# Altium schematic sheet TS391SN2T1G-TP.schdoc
size 127 x 101 mm
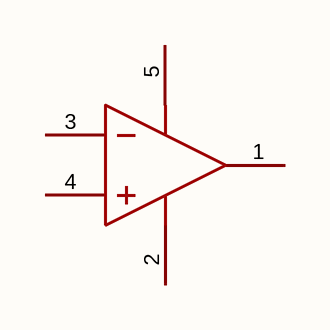
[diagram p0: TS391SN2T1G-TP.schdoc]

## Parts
U?  ts391sn2t1g-tp  [SOT-23-5_L3.0-W1.6-P0.95-LS2.8-BR]  (value not drawn)

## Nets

Not connected (* = marked no-connect by the designer): U? 1(OUT) 2(V-) 3(-IN) 4(+IN) 5(V+)

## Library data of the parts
U? = ts391sn2t1g-tp: Manufacturer: TECH PUBLIC(台舟); AddInBom: yes; ModelId: 72410e292833493f86746b22636ce101; ModelTransform: 110.236,116.1415,0,0,0,0,0.002,0.001,0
